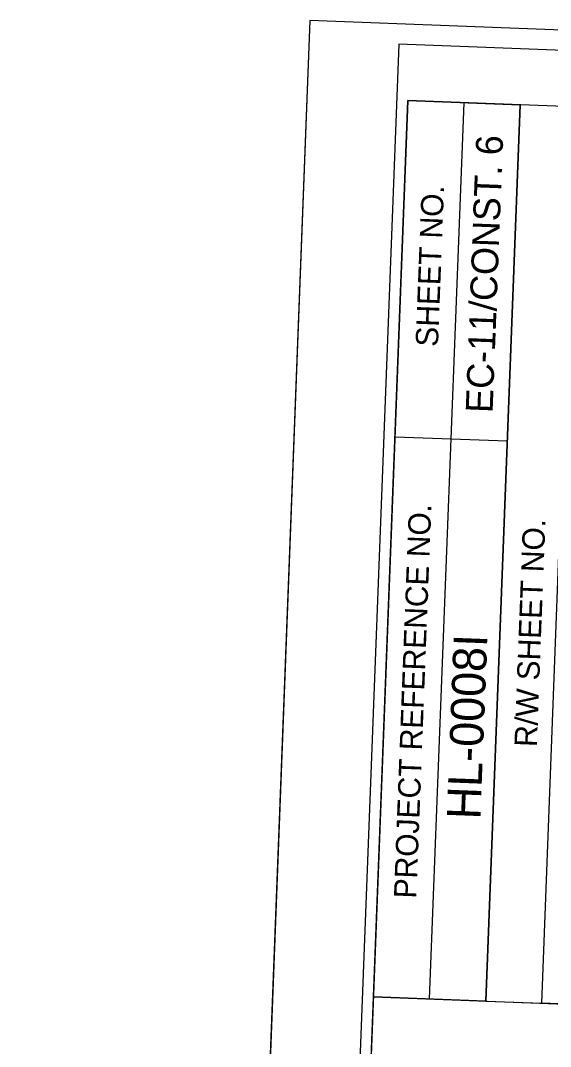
# Model space of a CAD drawing. Extents: x 2097083 to 2098242, y 681809 to 688195.
# Drawn here: x 2097083.2 to 2097201.4, y 687966 to 688194.8 of the extents above; entities that cross this region are included whole.
import ezdxf

# ---------------------------------------------------------------- set-up
doc = ezdxf.new("R2010")
doc.units = 0
for name, color, linetype in [('Sheet Cutting Line CELL', 7, 'Continuous'), ('Sheet Data Field CELL', 7, 'Continuous'), ('Sheet Plan CELL', 7, 'Continuous'), ('Sheet Plot Border Inside CELL', 7, 'Continuous'), ('Sheet Plot Border Outside CELL', 7, 'Continuous')]:
    doc.layers.add(name, color=color, linetype=linetype)

msp = doc.modelspace()

# ---------------------------------------------------------------- linework, layer by layer
at = {"layer": 'Sheet Cutting Line CELL'}
msp.add_line((2097147.77, 688194.8), (2097083.25, 686512.54), dxfattribs=at)
at = {"layer": 'Sheet Plan CELL'}
for p, q in [((2097174.45, 687976.56), (2097182.13, 688176.46)), ((2097186.98, 687976.09), (2097194.62, 688175.98)), ((2097186.98, 687976.09), (2097194.62, 688175.98)), ((2097166.77, 688101.97), (2097191.76, 688101.06)), ((2097186.98, 687976.09), (2097199.45, 687975.61))]:
    msp.add_line(p, q, dxfattribs=at)
for points in [[(2097169.59, 688176.98), (2097112.1, 686678.04), (2098161.33, 686637.81), (2098218.82, 688136.72)], [(2097161.91, 687977.05), (2097169.59, 688176.98), (2097194.62, 688175.98), (2097186.98, 687976.09)], [(2098161.33, 686637.81), (2097112.13, 686678.02), (2097161.91, 687977.05), (2097311.86, 687971.31), (2097319.54, 688171.2), (2098218.82, 688136.72)], [(2097199.45, 687975.61), (2097203.29, 688075.59), (2097315.72, 688071.28), (2097311.86, 687971.31)]]:
    msp.add_lwpolyline(points, close=True, dxfattribs=at)
at = {"layer": 'Sheet Plot Border Inside CELL'}
msp.add_lwpolyline([(2098157.96, 686484.33), (2098221.79, 688149.1), (2097167.58, 688189.54), (2097103.73, 686524.77)], close=True, dxfattribs=at)
at = {"layer": 'Sheet Plot Border Outside CELL'}
msp.add_lwpolyline([(2098177.45, 686470.58), (2098241.96, 688152.84), (2097147.77, 688194.8), (2097083.25, 686512.54)], close=True, dxfattribs=at)

# ---------------------------------------------------------------- texts
at = {"layer": 'Sheet Data Field CELL'}
for s, height, p in [('EC-11/CONST. 6', 6, (2097188.48, 688107.19)), ('HL-0008I', 7.5, (2097185.76, 688016.52))]:
    msp.add_text(s, height=height, rotation=87.8037, dxfattribs=at).set_placement(p)
at = {"layer": 'Sheet Plan CELL'}
for s, height, p in [('SHEET NO.', 5, (2097176.31, 688121.97)), ('PROJECT REFERENCE NO.', 5.0001, (2097171.48, 687998.9)), ('R/W SHEET NO.', 5.0001, (2097198.34, 688032.7))]:
    msp.add_text(s, height=height, rotation=87.8037, dxfattribs=at).set_placement(p)

doc.saveas('drawing.dxf')
